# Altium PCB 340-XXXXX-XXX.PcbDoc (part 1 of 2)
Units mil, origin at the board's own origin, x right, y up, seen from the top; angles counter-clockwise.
Board outline 2825 x 4480 mil, 2 copper layers (Top Layer, Bottom Layer), stack 60.8 mil thick; 87 components, 73 nets, 344 pads, 146 vias.
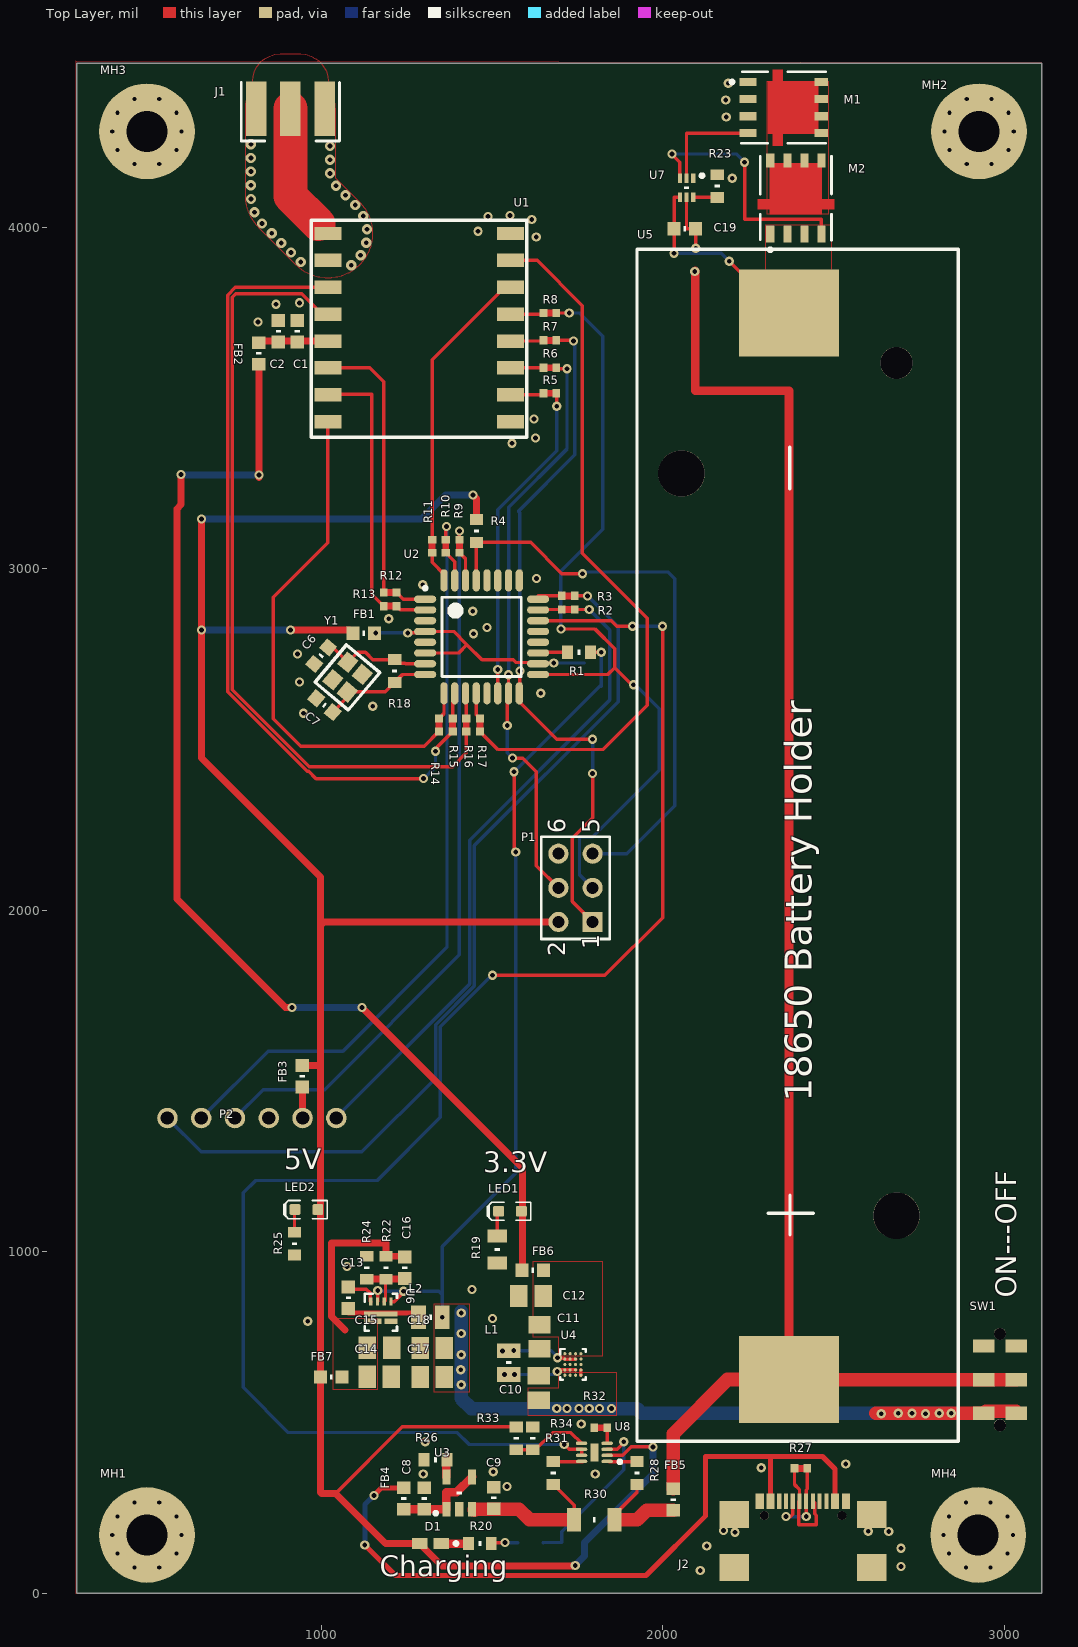
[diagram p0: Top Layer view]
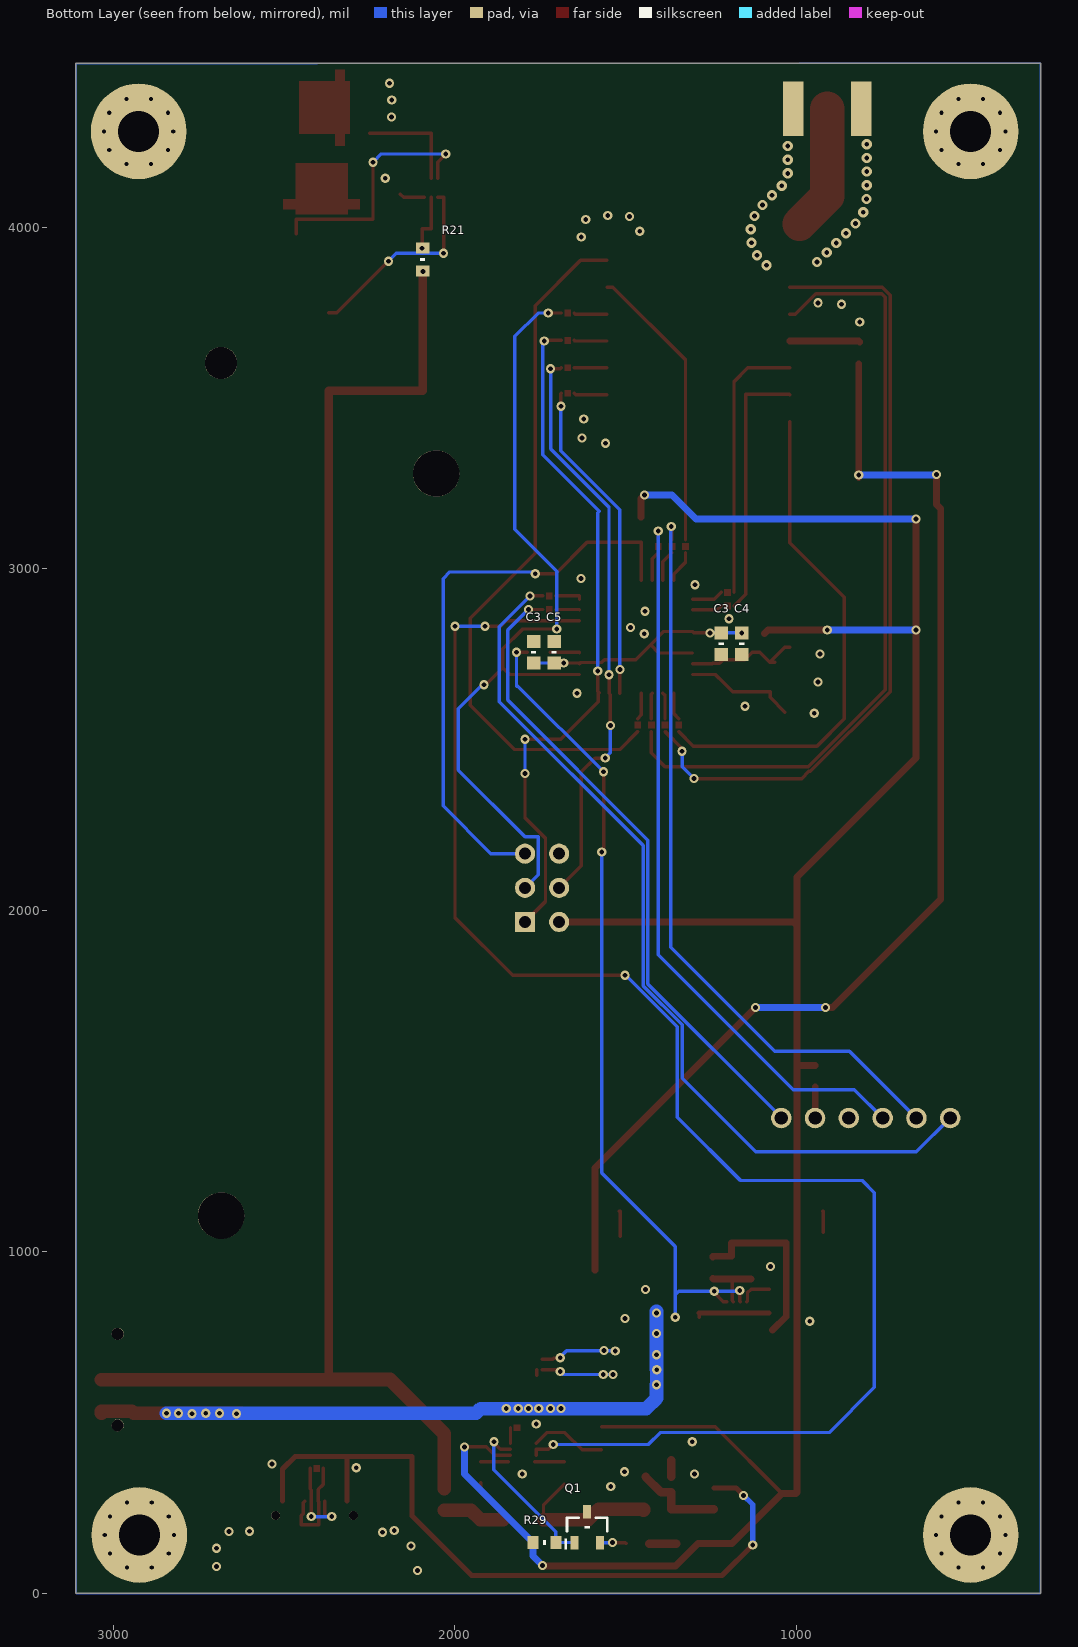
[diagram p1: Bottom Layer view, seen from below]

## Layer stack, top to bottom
Top Solder: solder mask 0.4, Solder Resist, Dk 3.5
Top Layer: signal copper 1.4
Dielectric1: core 58, FR-4, Dk 4.8
Bottom Layer: signal copper 1.4
Bottom Solder: solder mask 0.4, Solder Resist, Dk 3.5

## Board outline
285,0 3110,0 3110,4480 285,4480

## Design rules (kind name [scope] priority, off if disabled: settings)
AcuteAngle [All] p1: minimum=5.50000000000000E+0001 checktracksonly=FALSE
Clearance "50 Ohms" [InNetClass('50 Ohms')] p1: gap=50 ignorepadtopadclearanceinfootprint=FALSE
Clearance LAYER4-GND [InNamedPolygon('LAYER4-GND')] p2: gap=9.84 ignorepadtopadclearanceinfootprint=FALSE except(0: Arc-Hole Track-Hole SMDPad-Hole THPad-Hole Via-Hole Fill-Hole Poly-Hole Region-Hole Text-Hole)
Clearance BOT-GND [InNamedPolygon('BOT-GND')] p3: gap=9.84 ignorepadtopadclearanceinfootprint=FALSE except(0: Arc-Hole Track-Hole SMDPad-Hole THPad-Hole Via-Hole Fill-Hole Poly-Hole Region-Hole Text-Hole)
Clearance LAYER3-GND [InNamedPolygon('LAYER3-GND')] p4: gap=9.84 ignorepadtopadclearanceinfootprint=FALSE except(0: Arc-Hole Track-Hole SMDPad-Hole THPad-Hole Via-Hole Fill-Hole Poly-Hole Region-Hole Text-Hole)
Clearance LAYER1-GND [InNamedPolygon('LAYER1-GND')] p5: gap=9.84 ignorepadtopadclearanceinfootprint=FALSE except(0: Arc-Hole Track-Hole SMDPad-Hole THPad-Hole Via-Hole Fill-Hole Poly-Hole Region-Hole Text-Hole)
Clearance TOP-GND [InNamedPolygon('TOP-GND')] p6: gap=9.84 ignorepadtopadclearanceinfootprint=FALSE except(0: Arc-Hole Track-Hole SMDPad-Hole THPad-Hole Via-Hole Fill-Hole Poly-Hole Region-Hole Text-Hole)
Clearance LAYER2-GND [InNamedPolygon('LAYER2-GND')] p7: gap=9.84 ignorepadtopadclearanceinfootprint=FALSE except(0: Arc-Hole Track-Hole SMDPad-Hole THPad-Hole Via-Hole Fill-Hole Poly-Hole Region-Hole Text-Hole)
Clearance Clearance_DIFF [(InDifferentialPairClass('All Differential Pairs')) vs (InDifferentialPairClass('All Differential Pairs'))] p8: gap=3.94 ignorepadtopadclearanceinfootprint=FALSE except(0: Arc-Hole Track-Hole SMDPad-Hole THPad-Hole Via-Hole Fill-Hole Poly-Hole Region-Hole Text-Hole; 4.25: Arc-Via Track-Via; 4.96: SMDPad-Via; 5: Via-Via Via-Fill Via-Poly Via-Region Via-Text; 6.89: THPad-Via)
Clearance [All] p9: gap=3.94 ignorepadtopadclearanceinfootprint=FALSE except(0: Arc-Hole Track-Hole SMDPad-Hole THPad-Hole Via-Hole Fill-Hole Poly-Hole Region-Hole Text-Hole; 5: Via-Via Via-Fill Via-Poly Via-Region Via-Text; 6.89: THPad-Via)
ComponentClearance [All] p1 off: gap=10 collisioncheckmode=3 verticalgap=10 showdistances=FALSE
ComponentClearance ComponentClearance_Place [All] p2 off: gap=0 collisioncheckmode=3 verticalgap=10 showdistances=FALSE
ComponentClearance ComponentClearance_JTAG [HasFootprint('TP-600') vs HasFootprint('TP-600')] p3 off: gap=600.39 collisioncheckmode=3 verticalgap=9.84 showdistances=FALSE
ComponentClearance ComponentClearance_TP [InComponent('TP57') Or InComponent('TP60') vs InComponent('TP58') or InComponent('tp61')] p4 off: gap=0 collisioncheckmode=3 verticalgap=9.84 showdistances=FALSE
ComponentClearance ComponentClearance_SHORT [HasFootprint('SHORT-CIRCUIT') vs HasFootprint('SHORT-CIRCUIT')] p5 off: gap=0 collisioncheckmode=3 verticalgap=9.84 showdistances=FALSE
ComponentClearance ComponentClearance_TIEBAR [HasFootprint('TIEBAR-3N') vs HasFootprint('TIEBAR-3N')] p6 off: gap=0 collisioncheckmode=3 verticalgap=9.84 showdistances=FALSE
DiffPairsRouting Diff_90Ohm_USB [InDifferentialPairClass('Diff_USB')] p1: maxlimit=5.5 minlimit=5.5 mostfreqgap=5.5 toplayer_minwidth=9 toplayer_maxwidth=9 toplayer_prefwidth=9 bottomlayer_minwidth=9 bottomlayer_maxwidth=9 bottomlayer_prefwidth=9 maxuncoupledlength=150
DiffPairsRouting Diff_90Ohm_RF [InDifferentialPairClass('Diff_RF')] p2: maxlimit=5.5 minlimit=5.5 mostfreqgap=5.5 toplayer_minwidth=9 toplayer_maxwidth=9 toplayer_prefwidth=9 bottomlayer_minwidth=9 bottomlayer_maxwidth=9 bottomlayer_prefwidth=9 maxuncoupledlength=255
DiffPairsRouting Diff_100Ohm [InDifferentialPairClass('Diff_Ethernet')] p3: maxlimit=7 minlimit=7 mostfreqgap=7 toplayer_minwidth=8 toplayer_maxwidth=8 toplayer_prefwidth=8 bottomlayer_minwidth=8 bottomlayer_maxwidth=8 bottomlayer_prefwidth=8 maxuncoupledlength=400
DiffPairsRouting [(InDifferentialPairClass('All Differential Pairs'))] p4: maxlimit=74.8 minlimit=3.94 mostfreqgap=9.84 toplayer_minwidth=3.94 toplayer_maxwidth=15 toplayer_prefwidth=15 bottomlayer_minwidth=3.94 bottomlayer_maxwidth=15 bottomlayer_prefwidth=15 maxuncoupledlength=400
Height [All] p1 off: minheight=0 maxheight=984.25 prefheight=492.13
HoleSize [All] p1: absolutevalues=TRUE maxlimit=492.13 minlimit=7.87 maxpercent=80.000 minpercent=20.000
HoleToHoleClearance HoleToHoleClearance_TIEBAR [HasFootprint('TIEBAR-3N') vs HasFootprint('TIEBAR-3N')] p1: gap=0 allowstackedmicrovias=TRUE
HoleToHoleClearance [All] p2: gap=9.84 allowstackedmicrovias=TRUE
MatchedLengths MatchedLengths_DDS-DATA [InNetClass('DSS_DATA')] p1: tolerance=250 checknetsindiffpair=TRUE checkdiffpairvsdiffpair=FALSE checkxsignals=FALSE checkothers=FALSE
MatchedLengths MatchedLengths_FPGA_D [InNetClass('FPGA_D[15..0]')] p2: tolerance=1500 checknetsindiffpair=TRUE checkdiffpairvsdiffpair=FALSE checkxsignals=FALSE checkothers=FALSE
MatchedLengths MatchedLengths_FPGA_A [InNetClass('FPGA_A[10..1]')] p3: tolerance=1500 checknetsindiffpair=TRUE checkdiffpairvsdiffpair=FALSE checkxsignals=FALSE checkothers=FALSE
MatchedLengths MatchedLengths_SDRC_A1/2 [(InNetClass('SDRC_A1') OR InNetClass('SDRC_A2'))] p4: tolerance=25 checknetsindiffpair=TRUE checkdiffpairvsdiffpair=FALSE checkxsignals=FALSE checkothers=FALSE
MatchedLengths MatchedLengths_SDRC_A2 [InNetClass('SDRC_A2')] p5: tolerance=25 checknetsindiffpair=TRUE checkdiffpairvsdiffpair=FALSE checkxsignals=FALSE checkothers=FALSE
MatchedLengths MatchedLengths_SDRC_A1 [InNetClass('SDRC_A1')] p6: tolerance=25 checknetsindiffpair=TRUE checkdiffpairvsdiffpair=FALSE checkxsignals=FALSE checkothers=FALSE
MatchedLengths MatchedLengths_SDRC_D [InNetClass('SDRC_D')] p7: tolerance=25 checknetsindiffpair=TRUE checkdiffpairvsdiffpair=FALSE checkxsignals=FALSE checkothers=FALSE
MatchedLengths MatchedLengths_SDRC_A [InNetClass('SDRC_A')] p8: tolerance=25 checknetsindiffpair=TRUE checkdiffpairvsdiffpair=FALSE checkxsignals=FALSE checkothers=FALSE
MinimumAnnularRing MinimumAnnularRing_203 [(AsMM(HoleDiameter) = 0.203)] p1: minimumring=4.92
MinimumAnnularRing MinimumAnnularRing_381 [((ObjectKind = 'Via') And (AsMM(HoleDiameter) = 0.381))] p2: minimumring=4.92
MinimumAnnularRing [All] p3: minimumring=6
MinimumSolderMaskSliver "USB-C SM Clearence" [InComponent('J2')] p1: minsoldermaskwidth=3.94
MinimumSolderMaskSliver [All] p2: minsoldermaskwidth=4.53
PlaneClearance [All] p1: clearance=10
PlaneConnect [All] p1: planeconnectstyle=Relief reliefexpansion=5 reliefentries=4 reliefconductorwidth=12 reliefairgap=6
PolygonConnect [All] p1: thpad.connectstyle=Relief thpad.reliefconductorwidth=12 thpad.reliefentries=4 thpad.polygonreliefangle="45 Angle" thpad.airgapwidth=6 smdpad.connectstyle=Direct smdpad.reliefconductorwidth=12 smdpad.reliefentries=4 smdpad.polygonreliefangle="90 Angle" smdpad.airgapwidth=6 via.connectstyle=Direct via.reliefconductorwidth=6 via.reliefentries=4 via.polygonreliefangle="45 Angle" via.airgapwidth=4
RoomDefinition "01 - Main" [InComponentClass('01 - Main')] p1: confinementstyle=ConfineIn formatcopy=TRUE lockcomponents=FALSE outline -10140,-6860 -8140,-6860 -8140,-5860 -10140,-5860
RoutingCorners [All] p1: cornerstyle=45-Degree minsetback=50 maxsetback=100
RoutingPriority [(InDifferentialPairClass('All Differential Pairs'))] p1: routingpriority=1
RoutingTopology RoutingTopology_BOT [OnLayer('Bottom Layer')] p1: topology=Shortest
RoutingTopology RoutingTopology_LR4 [OnLayer('MidLayer4')] p2: topology=Vertical
RoutingTopology RoutingTopology_LR3 [OnLayer('MidLayer3')] p3: topology=Horizontal
RoutingTopology RoutingTopology_LR2 [OnLayer('MidLayer2')] p4: topology=Vertical
RoutingTopology RoutingTopology_LR1 [OnLayer('MidLayer1')] p5: topology=Horizontal
RoutingTopology RoutingTopology_TOP [OnLayer('Top Layer')] p6: topology=Shortest
RoutingTopology [All] p7: topology=Shortest
RoutingVias [All] p1: holewidth=8 width=18 viastyle="Through Hole" minholewidth=8 minwidth=18 maxholewidth=125 maxwidth=340
ShortCircuit ShortCircuit_SHORTS [(InNet('GND') OR InNet('SGND1') OR InNet('SGND2') OR InNet('SGND3') OR InNet('SGND4')and InPADClass(SHORTS)) vs (InNet('GND') OR InNet('SGND1') OR InNet('SGND2') OR InNet('SGND3') OR InNet('SGND4')AND InPADClass(SHORTS))] p1: allowed=TRUE
ShortCircuit ShortCircuit_TIEBAR-PP [InPadClass('TIE BAR') vs InPadClass('TIE BAR')] p2: allowed=TRUE
ShortCircuit ShortCircuit_TIEBAR-TP [InNetClass('SDRC_A1')OR InNetClass('SDRC_A2')OR InNetClass('SDRC_A') vs InPadClass('TIE BAR')] p3: allowed=TRUE
ShortCircuit ShortCircuit_A14 [(InNet('SDRC_A14') OR InNet('SDRC_A14-1') OR InNet('SDRC_A14-2')) vs (InNet('SDRC_A14') OR InNet('SDRC_A14-1') OR InNet('SDRC_A14-2'))] p4: allowed=TRUE
ShortCircuit ShortCircuit_A13 [(InNet('SDRC_A13') OR InNet('SDRC_A13-1') OR InNet('SDRC_A13-2')) vs (InNet('SDRC_A13') OR InNet('SDRC_A13-1') OR InNet('SDRC_A13-2'))] p5: allowed=TRUE
ShortCircuit ShortCircuit_A12 [(InNet('SDRC_A12') OR InNet('SDRC_A12-1') OR InNet('SDRC_A12-2')) vs (InNet('SDRC_A12') OR InNet('SDRC_A12-1') OR InNet('SDRC_A12-2'))] p6: allowed=TRUE
ShortCircuit ShortCircuit_A11 [(InNet('SDRC_A11') OR InNet('SDRC_A11-1') OR InNet('SDRC_A11-2')) vs (InNet('SDRC_A11') OR InNet('SDRC_A11-1') OR InNet('SDRC_A11-2'))] p7: allowed=TRUE
ShortCircuit ShortCircuit_A10 [(InNet('SDRC_A10') OR InNet('SDRC_A10-1') OR InNet('SDRC_A10-2')) vs (InNet('SDRC_A10') OR InNet('SDRC_A10-1') OR InNet('SDRC_A10-2'))] p8: allowed=TRUE
ShortCircuit ShortCircuit_A9 [(InNet('SDRC_A9') OR InNet('SDRC_A9-1') OR InNet('SDRC_A9-2')) vs (InNet('SDRC_A9') OR InNet('SDRC_A9-1') OR InNet('SDRC_A9-2'))] p9: allowed=TRUE
ShortCircuit ShortCircuit_A8 [(InNet('SDRC_A8') OR InNet('SDRC_A8-1') OR InNet('SDRC_A8-2')) vs (InNet('SDRC_A8') OR InNet('SDRC_A8-1') OR InNet('SDRC_A8-2'))] p10: allowed=TRUE
ShortCircuit ShortCircuit_A7 [(InNet('SDRC_A7') OR InNet('SDRC_A7-1') OR InNet('SDRC_A7-2')) vs (InNet('SDRC_A7') OR InNet('SDRC_A7-1') OR InNet('SDRC_A7-2'))] p11: allowed=TRUE
ShortCircuit ShortCircuit_A6 [(InNet('SDRC_A6') OR InNet('SDRC_A6-1') OR InNet('SDRC_A6-2')) vs (InNet('SDRC_A6') OR InNet('SDRC_A6-1') OR InNet('SDRC_A6-2'))] p12: allowed=TRUE
ShortCircuit ShortCircuit_A5 [(InNet('SDRC_A5') OR InNet('SDRC_A5-1') OR InNet('SDRC_A5-2')) vs (InNet('SDRC_A5') OR InNet('SDRC_A5-1') OR InNet('SDRC_A5-2'))] p13: allowed=TRUE
ShortCircuit ShortCircuit_A4 [(InNet('SDRC_A4') OR InNet('SDRC_A4-1') OR InNet('SDRC_A4-2')) vs (InNet('SDRC_A4') OR InNet('SDRC_A4-1') OR InNet('SDRC_A4-2'))] p14: allowed=TRUE
ShortCircuit ShortCircuit_A3 [(InNet('SDRC_A3') OR InNet('SDRC_A3-1') OR InNet('SDRC_A3-2')) vs (InNet('SDRC_A3') OR InNet('SDRC_A3-1') OR InNet('SDRC_A3-2'))] p15: allowed=TRUE
ShortCircuit ShortCircuit_A2 [(InNet('SDRC_A2') OR InNet('SDRC_A2-1') OR InNet('SDRC_A2-2')) vs (InNet('SDRC_A2') OR InNet('SDRC_A2-1') OR InNet('SDRC_A2-2'))] p16: allowed=TRUE
ShortCircuit ShortCircuit_A1 [(InNet('SDRC_A1') OR InNet('SDRC_A1-1') OR InNet('SDRC_A1-2')) vs (InNet('SDRC_A1') OR InNet('SDRC_A1-1') OR InNet('SDRC_A1-2'))] p17: allowed=TRUE
ShortCircuit ShortCircuit_A0 [(InNet('SDRC_A0') OR InNet('SDRC_A0-1') OR InNet('SDRC_A0-2')) vs (InNet('SDRC_A0') OR InNet('SDRC_A0-1') OR InNet('SDRC_A0-2'))] p18: allowed=TRUE
ShortCircuit ShortCircuit_BA0 [(InNet('SDRC_BA0') OR InNet('SDRC_BA0-1') OR InNet('SDRC_BA0-2')) vs (InNet('SDRC_BA0') OR InNet('SDRC_BA0-1') OR InNet('SDRC_BA0-2'))] p19: allowed=TRUE
ShortCircuit ShortCircuit_BA1 [(InNet('SDRC_BA1') OR InNet('SDRC_BA1-1') OR InNet('SDRC_BA1-2')) vs (InNet('SDRC_BA1') OR InNet('SDRC_BA1-1') OR InNet('SDRC_BA1-2'))] p20: allowed=TRUE
ShortCircuit ShortCircuit_BA2 [(InNet('SDRC_BA2') OR InNet('SDRC_BA2-1') OR InNet('SDRC_BA2-2')) vs (InNet('SDRC_BA2') OR InNet('SDRC_BA2-1') OR InNet('SDRC_BA2-2'))] p21: allowed=TRUE
ShortCircuit ShortCircuit_CLK_P [(InNet('SDRC_CLK_P') OR InNet('SDRC_CLK-1_P') OR InNet('SDRC_CLK-2_P')) vs (InNet('SDRC_CLK_P') OR InNet('SDRC_CLK-1_P') OR InNet('SDRC_CLK-2_P'))] p22: allowed=TRUE
ShortCircuit ShortCircuit_CLK_N [(InNet('SDRC_CLK_N') OR InNet('SDRC_CLK-1_N') OR InNet('SDRC_CLK-2_N')) vs (InNet('SDRC_CLK_N') OR InNet('SDRC_CLK-1_N') OR InNet('SDRC_CLK-2_N'))] p23: allowed=TRUE
ShortCircuit ShortCircuit_CLKE0 [(InNet('SDRC_CKE0') OR InNet('SDRC_CKE0-1') OR InNet('SDRC_CKE0-2')) vs (InNet('SDRC_CKE0') OR InNet('SDRC_CKE0-1') OR InNet('SDRC_CKE0-2'))] p24: allowed=TRUE
ShortCircuit ShortCircuit_NCS0 [(InNet('SDRC_NCS0') OR InNet('SDRC_NCS0-1') OR InNet('SDRC_NCS0-2')) vs (InNet('SDRC_NCS0') OR InNet('SDRC_NCS0-1') OR InNet('SDRC_NCS0-2'))] p25: allowed=TRUE
ShortCircuit ShortCircuit_NRAS [(InNet('SDRC_NRAS') OR InNet('SDRC_NRAS-1') OR InNet('SDRC_NRAS-2')) vs (InNet('SDRC_NRAS') OR InNet('SDRC_NRAS-1') OR InNet('SDRC_NRAS-2'))] p26: allowed=TRUE
ShortCircuit ShortCircuit_NCAS [(InNet('SDRC_NCAS') OR InNet('SDRC_NCAS-1') OR InNet('SDRC_NCAS-2')) vs (InNet('SDRC_NCAS') OR InNet('SDRC_NCAS-1') OR InNet('SDRC_NCAS-2'))] p27: allowed=TRUE
ShortCircuit ShortCircuit_NWE [(InNet('SDRC_NWE') OR InNet('SDRC_NWE-1') OR InNet('SDRC_NWE-2')) vs (InNet('SDRC_NWE') OR InNet('SDRC_NWE-1') OR InNet('SDRC_NWE-2'))] p28: allowed=TRUE
ShortCircuit [All] p29: allowed=FALSE
SilkToSilkClearance [All] p1: silktosilkclearance=0
SilkToSolderMaskClearance SilkscreenOverComponentPads [IsPad] p1: minsilkscreentomaskgap=1.5 clearancetoexposedcopper=FALSE
SolderMaskExpansion SolderMaskExpansion_VIA [IsVia] p1: expansion=-1.97
SolderMaskExpansion [IsPad] p2: expansion=1.57
SolderMaskExpansion SolderMaskExpansion_1 [All] p3: expansion=1.57
ViasUnderSMD [All] p1 off: allowed=FALSE
Width [All] p1: maxlimit=120 minlimit=3.94 preferedwidth=8 minimp=50.000000 maximp=50.000000 favimp=50.000000
16 further rules are at their usual default settings.

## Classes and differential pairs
net class "50 Ohms": NetJ1_1

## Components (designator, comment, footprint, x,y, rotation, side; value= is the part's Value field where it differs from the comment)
C1 "0.1µF" CAPC1608X95N 930,3695 r90 top
C2 "1.0µF" CAPC1608X95N 875,3695 r90 top
C3 "1.0µF" CAPC1608X95N 1770,2755 r90 bottom
C3 "0.1µF" CAPC1608X95N 1220,2780 r270 bottom
C4 "0.1µF" CAPC1608X95N 1160,2780 r270 bottom
C5 "0.1µF" CAPC1608X95N 1710,2755 r90 bottom
C6 "27pF" CAPC1608X95N 1000,2745 r50 top
C7 "27pF" CAPC1608X95N 1010,2600 r320 top
C8 "1.0µF" CAPC1608X95N 1301.77,276.61 r90 top
C9 "1.0µF" CAPC1608X95N 1506.02,278.62 r90 top
C10 "10µF" CAPC2013X140N 1637,600.57 r90 top
C11 "10µF" CAPC2013X140N 1639,750.43 r270 top
C12 "47µF" CAPC2013X140N 1614.57,870 r180 top
C13 "10nF" CAPC1608X95N 1080,865 r270 top
C14 "22µF" CAPC2013X140N 1170.47,633.15 r0 top
C15 "22µF" CAPC2013X140N 1170.91,718.15 r0 top
C16 "10pF" CAPC1608X95N 1245,952.68 r270 top
C17 "10µF" CAPC2013X140N 1325,632.68 r180 top
C18 "10µF" CAPC2013X140N 1325,717.68 r180 top
C19 "0.1µF" CAPC1608X95N 2065,3995 r180 top
D1 "APT1608SRCPRV" LEDM1608X90N 1320,145 r180 top
FB1 "BLM18PG121SN1D" INDC1608X95N 1125,2810 r0 top
FB2 "BLM18PG121SN1D" INDC1608X95N 817.72,3630 r270 top
FB3 "BLM18PG121SN1D" INDC1608X95N 945,1513 r270 top
FB4 "BLM18PG121SN1D" INDC1608X95N 1241.77,276.61 r90 top
FB5 "BLM18PG121SN1D" INDC1608X95N 2031.02,273.62 r90 top
FB6 "BLM18PG121SN1D" INDC1608X95N 1620,945 r180 top
FB7 "BLM18PG121SN1D" INDC1608X95N 1030,632.68 r180 top
J1 "CONSMA003.062" LINX_CONSMA003.062 910,4435 r0 top
J2 "USB-C USB 2.0" GCT_USB4110-GF-A 2284.45,269.32 r0 top
L1 "1uH" INDC2016X10N 1549,675 r90 top
L2 "1uH" INDC2016X10N 1320,807.68 r180 top
LED1 "Green" LED-0603-GREEN 1553,1118 r180 top
LED2 "Green" LED-0603-GREEN 957,1123 r180 top
M1 "BSS138" VISHAY_POWERPAK-SO-8-SINGLE 2355,4350 r0 top
M2 "BSS138" VISHAY_POWERPAK-SO-8-SINGLE 2390,4085 r90 top
MH1 "MOUNTING HOLE" MHOLE-120-280 490,170 r0 top
MH2 "MOUNTING HOLE" MHOLE-120-280 2926.56,4280 r0 top
MH3 "MOUNTING HOLE" MHOLE-120-280 490,4280 r0 top
MH4 "MOUNTING HOLE" MHOLE-120-280 2924.06,170 r0 top
P1 "Header 3X2" HDR2X3 1795,1965 r90 top
P2 "BT_Header" BT_MODULE 1044.49,1391 r180 top
Q1 "MMBT3906" SOT95P240X115-3N 1613,193 r90 bottom
R1 "100K" RESC1608X84N 1755.28,2755 r180 top
R2 "0" RESC1005X40N_SHORT 1723.9,2880 r180 top net-tie
R3 "0" RESC1005X40N_SHORT 1723.9,2920 r180 top net-tie
R4 "10K" RESC1608X84N 1455,3110 r270 top
R5 "0" RESC1005X40N_SHORT 1670,3513.19 r180 top net-tie
R6 "0" RESC1005X40N_SHORT 1670,3588.19 r180 top net-tie
R7 "0" RESC1005X40N_SHORT 1670,3668.19 r180 top net-tie
R8 "0" RESC1005X40N_SHORT 1670,3748.19 r180 top net-tie
R9 "0" RESC1005X40N_SHORT 1405,3065 r270 top net-tie
R10 "0" RESC1005X40N_SHORT 1365,3065 r270 top net-tie
R11 "0" RESC1005X40N_SHORT 1325,3065 r270 top net-tie
R12 "0" RESC1005X40N_SHORT 1201.81,2930 r0 top net-tie
R13 "0" RESC1005X40N_SHORT 1201.81,2890 r0 top net-tie
R14 "0" RESC1005X40N_SHORT 1345,2541.81 r90 top net-tie
R15 "0" RESC1005X40N_SHORT 1385,2541.81 r90 top net-tie
R16 "0" RESC1005X40N_SHORT 1425,2541.81 r90 top net-tie
R17 "0" RESC1005X40N_SHORT 1465,2541.81 r90 top net-tie
R18 "1.0MEG" RESC1608X84N 1215,2700 r270 top
R19 "330" RESC2013X84N 1516,1006 r270 top
R20 "510" RESC1608X84N 1465,145 r0 top
R21 "330" RESC1608X84N 2095,3905 r90 bottom
R22 "316K" RESC1608X84N 1190,952.68 r270 top
R23 "2.2K" RESC1608X84N 2160,4120 r90 top
R24 "100K" RESC1608X84N 1133.19,952.68 r90 top
R25 "510" RESC1608X84N 922,1023 r270 top
R26 "2.00K" RESC1608X84N 1335,390 r180 top
R27 "0" RESC1005X40N_SHORT 2405,365 r180 top net-tie
R28 "5.1" RESC1608X84N 1925,351.54 r90 top
R29 "10K" RESC1608X84N 1738,148 r180 bottom
R30 "50m" RESC3216X84N 1800,215 r180 top
R31 "5.1" RESC1608X84N 1680,351.54 r90 top
R32 "0" RESC1005X40N_SHORT 1818.5,484 r0 top net-tie
R33 "100K" RESC1608X84N 1571,453 r270 top
R34 "4.02K" RESC1608X84N 1620,453 r90 top
SW1 "SWITCH" JS202011JAQN 2940.51,526.57 r90 top
U1 "RFM69" RFM69HCW 1555,3430 r180 top
U2 "ATmega328P-AUR" 32A_N 1470,2800 r0 top
U3 "MCP73812" SOT95P280X145-5N 1404.37,292.87 r90 top
U4 "TPS630242YFFR" YFF0020AEBA 1737.13,669.25 r0 top value=N/A
U5 "18650" 18650 2370.04,625.08 r90 top
U6 "N/A" RNS0007A 1175,817.68 r0 top
U7 "BQ29702DSER" SOTFL50P162X60-6N 2070,4115 r270 top
U8 "INA381" SON45P200X200X80-9N 1800,412 r180 top
Y1 "16 MHz" Crystal_2.5x2.0 1077.78,2725.43 r230 top

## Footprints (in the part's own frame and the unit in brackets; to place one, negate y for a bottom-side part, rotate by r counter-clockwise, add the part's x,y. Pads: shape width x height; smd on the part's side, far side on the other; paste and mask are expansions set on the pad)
32A_N [mm] "Thin QFP, 32-Leads, Body 7x7mm, Pitch 0.8mm, IPC Medium Density"
  oval 1.65x0.55 smd: 1(-4.2,2.8) 2(-4.2,2) 3(-4.2,1.2) 4(-4.2,0.4) 5(-4.2,-0.4) 6(-4.2,-1.2) 7(-4.2,-2) 8(-4.2,-2.8) 17(4.2,-2.8) 18(4.2,-2) 19(4.2,-1.2) 20(4.2,-0.4) 21(4.2,0.4) 22(4.2,1.2) 23(4.2,2) 24(4.2,2.8)
  oval 0.55x1.65 smd: 9(-2.8,-4.2) 10(-2,-4.2) 11(-1.2,-4.2) 12(-0.4,-4.2) 13(0.4,-4.2) 14(1.2,-4.2) 15(2,-4.2) 16(2.8,-4.2) 25(2.8,4.2) 26(2,4.2) 27(1.2,4.2) 28(0.4,4.2) 29(-0.4,4.2) 30(-1.2,4.2) 31(-2,4.2) 32(-2.8,4.2)
  silkscreen extent -4.32,-2.95 2.95,3.75, body extent -3.5,-3.5 3.5,3.5, height 1.2
18650 [mm] "HOLDER BATTERY 1CELL 18650 SMD"
  round 3.45 hole 3.45: 0(12.19,-8) 0(67.39,8)
  round 2.39 hole 2.39: 0(75.61,-8)
  rect 6.47x7.46 smd: 1(0,0) 2(79.34,0)
  silkscreen extent -4.6,-12.6 84.07,11.3, body extent -3.15,-10.21 82.85,10.44, height 14.86
BT_MODULE [mil]
  round 60 hole 39.37: 1(0,0) 2(98.82,0) 3(197.64,0) 4(296.85,0) 5(395.67,0) 6(494.49,0)
CAPC1608X95N [mm] "Chip Capacitor, Body 1.6x0.8mm, IPC Medium Density (0603)"
  rect 0.95x1 smd: 1(-0.8,0) 2(0.8,0)
  silkscreen extent -0.1,-0.2 0.1,0.2, body extent -0.8,-0.4 0.8,0.4, height 0.95
CAPC2013X140N [mm] "Chip Capacitor, 2-Leads, Body 2.0x1.3mm, IPC Medium Density"
  rect 1.3x1.65 smd: 1(-0.9,0) 2(0.9,0)
  body extent -1.19,-0.82 1.19,0.82, height 1.4
Crystal_2.5x2.0 [mm]
  rect 1.2x1.1 smd: 1(0,0) 2(1.7,0) 3(1.7,1.4) 4(0,1.4)
  silkscreen extent -0.94,-0.91 2.69,2.31
GCT_USB4110-GF-A [mm]
  round 0.65 hole 0.65 paste+0 mask+0: 0(0.33,-1.075) 0(6.11,-1.075)
  rect 0.6x1.15 smd mask+0: A1(0,0) A4(0.8,0) A9(5.602,0) A12(6.402,0)
  rect 0.3x1.15 smd mask+0: A5(1.952,0) A6(2.952,0) A7(3.452,0) A8(4.452,0) B5(4.952,0) B6(3.952,0) B7(2.452,0) B8(1.45,0)
  rect 2.18x2 smd mask+0.05: H1(-1.89,-1) H2(8.33,-1) H4(8.33,-4.93)
  rect 2.18x2 smd paste+0 mask+0.05: H3(-1.89,-4.93)
  body extent -2.44,-10.19 8.86,0.31, height 3.23
HDR2X3 [mm] "Connector; Header; 3x2 Position"
  rect 1.5x1.5 hole 0.9: 1(0,0)
  round 1.5 hole 0.9: 2(0,2.54) 3(2.54,0) 4(2.54,2.54) 5(5.08,0) 6(5.08,2.54)
  silkscreen extent -1.27,-1.27 6.35,3.81
INDC1608X95N [mm] "Chip Inductor, 2-Leads, Body 1.6x0.8mm, IPC Medium Density"
  rect 0.95x1 smd: 1(-0.8,0) 2(0.8,0)
  silkscreen extent -0.1,-0.2 0.1,0.2, body extent -0.87,-0.47 0.87,0.47, height 0.95
INDC2016X10N [mm] "Chip Inductor, 2-Leads, Body 2.00x1.60mm, IPC Medium Density"
  rect 1.09x1.74 smd: 1(-0.885,0) 2(0.885,0)
  silkscreen extent -0.1,-0.2 0.1,0.2, body extent -1.05,-0.85 1.05,0.85, height 1
JS202011JAQN [mm]
  rect 1x1.6 smd: 1(0,0) 1(0,-2.4) 2(2.5,-2.4) 2(2.5,0) 3(5,-2.4) 3(5,0)
  round 0.9 hole 0.9 paste+0 mask+0: 4(-0.9,-1.2) 4(5.9,-1.2)
  body extent -2.03,-4.96 6.97,0.59, height 3.62
LED-0603-GREEN [mm]
  round 0.254 on Mech15: 0(0,0)
  rrect25% 0.8x0.8 smd: A(-0.85,0) K(0.85,0)
  Top Layer pour cut-out: -0.5,0.5 0.5,0.5 0.5,-0.5 -0.5,-0.5
  silkscreen extent -1.55,-0.68 1.68,0.68, body extent -0.8,-0.4 0.8,0.4, height 0.75
LEDM1608X90N [mm] "Molded LED, 2-Leads, Body 1.6x0.8mm, IPC Medium Density"
  rect 1.15x0.85 smd: A(0.8,0) C(-0.8,0)
  silkscreen extent -2.03,-0.12 -1.78,0.12, body extent -0.85,-0.45 0.85,0.45, height 0.9
LINX_CONSMA003.062 [mm] "CONN, SMA JACK FEMALE, 50 OHM, EDGE MNT"
  rect 1.52x4.06 smd: 1(0,-2.25) 2(-2.54,-2.25) 2(2.54,-2.25)
  rect 1.52x4.06 smd far side: 2(-2.54,-2.25) 2(2.54,-2.25)
  silkscreen extent -3.65,-4.65 3.65,-0.3, body extent -3.96,-3.9 3.96,7.64, height 4.62
MHOLE-120-280 [mil]
  round 25 hole 12 paste-1968.5 mask+2: 1(-101.56,0) 1(-85.94,-54.69) 1(-85.94,54.69) 1(-35.94,-95.31) 1(-35.94,95.31) 1(35.94,-95.31) 1(35.94,95.31) 1(85.94,-54.69) 1(85.94,54.69) 1(101.56,0)
  round 280 hole 120 paste-1968.5 mask+2: 1(0,0)
RESC1005X40N_SHORT [mm] "Chip Resistor, Body 1.0x0.5mm, IPC Medium Density"
  rect 0.57x0.62 smd: 1(-0.48,0) 2(0.48,0)
  Top Layer region: -0.254,-0.254 0.254,-0.254 0.254,0.254 -0.254,0.254
  body extent -0.55,-0.3 0.55,0.3, height 0.4
RESC1608X84N [mm] "Chip Resistor, Body 1.6x0.8mm, IPC Medium Density"
  rect 0.8x1 smd: 1(-0.85,0) 2(0.85,0)
  silkscreen extent -0.1,-0.2 0.1,0.2, body extent -0.8,-0.4 0.8,0.4, height 0.84
RESC2013X84N [mm] "Chip Resistor, 2-Leads, Body 2.0x1.3mm, IPC Medium Density"
  rect 0.95x1.45 smd: 1(-1,0) 2(1,0)
  silkscreen extent -0.1,-0.2 0.1,0.2, body extent -1.09,-0.7 1.09,0.7, height 0.84
RESC3216X84N [mm] "Chip Resistor, 2-Leads, Body 3.2x1.6mm, IPC Medium Density"
  rect 1.05x1.75 smd: 1(-1.5,0) 2(1.5,0)
  silkscreen extent -0.1,-0.2 0.1,0.2, body extent -1.67,-0.86 1.67,0.86, height 0.84
RFM69HCW [mm]
  rect 2x1 smd: 1(0,0) 2(0,-2) 3(0,-4) 4(0,-6) 5(0,-8) 6(0,-10) 7(0,-12) 8(0,-14) 9(13.6,-14) 10(13.6,-12) 11(13.6,-10) 12(13.6,-8) 13(13.6,-6) 14(13.6,-4) 15(13.6,-2) 16(13.6,0)
  silkscreen extent -1.19,-14.99 14.83,1.14, body extent -1.19,-14.96 14.81,1.14, height 1.8
RNS0007A [mm]
  rect 0.25x0.6 smd: 1(-0.75,0.9) 2(-0.25,0.9) 3(0.25,0.9) 4(0.75,0.9)
  rect 2.5x0.35 smd: 5(0,-0.015)
  rect 1x0.4 smd: 6(0.75,-0.54)
  rect 1.3x0.4 smd: 7(-0.6,-0.54)
  silkscreen extent -1.2,-1.25 1.2,1.5
SON45P200X200X80-9N [mm] "SMALL OUTLINE NO LEAD, 8-Leads, Body 2.1x2.1mm (max), Pitch 0.45mm, IPC Medium Density"
  oval 0.85x0.25 smd: 1(-0.95,0.675) 2(-0.95,0.225) 3(-0.95,-0.225) 4(-0.95,-0.675) 5(0.95,-0.675) 6(0.95,-0.225) 7(0.95,0.225) 8(0.95,0.675)
  rect 0.6x1.35 smd: 9(0,0)
  silkscreen extent -2.02,0.58 -1.78,0.82, body extent -1.1,-1.1 1.1,1.1, height 0.8
SOT95P240X115-3N [mm] "SOT23, 3-Leads, Body 3.0x2.5mm (max), Pitch 0.95mm, IPC Medium Density"
  rect 1x0.6 smd: 1(-1.15,0.95) 2(-1.15,-0.95) 3(1.15,0)
  silkscreen extent -1.65,-1.5 0.7,1.7, body extent -0.7,-1.5 0.7,1.5, height 1.15
SOT95P280X145-5N [mm] "SOT23, 5-Leads, Body 3.0x3.0mm (max), Pitch 0.95mm, IPC Medium Density"
  rect 1.1x0.6 smd: 1(-1.2,0.95) 2(-1.2,0) 3(-1.2,-0.95) 4(1.2,-0.95) 5(1.2,0.95)
  silkscreen extent -1.62,-0.2 0.1,1.87, body extent -0.85,-1.5 0.85,1.5, height 1.45
SOTFL50P162X60-6N [mm] "SC89"
  rect 0.71x0.3 smd mask+0.025: 1(-0.72,0.5) 2(-0.72,0) 3(-0.72,-0.5) 4(0.72,-0.5) 5(0.72,0) 6(0.72,0.5)
  silkscreen extent -1.02,-0.2 0.1,1.28, body extent -0.85,-0.85 0.85,0.85, height 0.6
VISHAY_POWERPAK-SO-8-SINGLE [mm] "MOSFET, N-CHANNEL, POWERPAK SO-8 SINGLE"
  rect 1.27x0.61 smd: 1(-2.675,1.9) 2(-2.675,0.625) 3(-2.675,-0.65) 4(-2.675,-1.9)
  rect 1.02x0.61 smd: D(2.79,-1.9) D(2.79,-0.65) D(2.79,0.625) D(2.79,1.9)
  Top Layer region: -0.838,1.93 -0.076,1.93 -0.076,2.845 -0.838,2.845
  Top Layer region: -0.838,-2.87 -0.076,-2.87 -0.076,-1.956 -0.838,-1.956
  Top Layer region: -1.219,-1.956 2.591,-1.956 2.591,1.956 -1.219,1.956
  silkscreen extent -3.97,-2.65 3.1,2.65, body extent -3.12,-2.65 3.12,2.65, height 1.12
YFF0020AEBA [mm]
  round 0.23 smd: 1(-0.6,0.8) 2(-0.2,0.8) 3(0.2,0.8) 4(0.6,0.8) 5(-0.6,0.4) 6(-0.2,0.4) 7(0.2,0.4) 8(0.6,0.4) 9(-0.6,0) 10(-0.2,0) 11(0.2,0) 12(0.6,0) 13(-0.6,-0.4) 14(-0.2,-0.4) 15(0.2,-0.4) 16(0.6,-0.4) 17(-0.6,-0.8) 18(-0.2,-0.8) 19(0.2,-0.8) 20(0.6,-0.8)
  silkscreen extent -0.95,-1.15 0.95,1.15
